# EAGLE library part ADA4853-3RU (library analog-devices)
Low Power, Rail-to-Rail Output, Video Op Amps with Ultralow Power Source: http://www.analog.com/static/imported-files/data_sheets/ADA4853-1_4853-2_4853-3.pdf
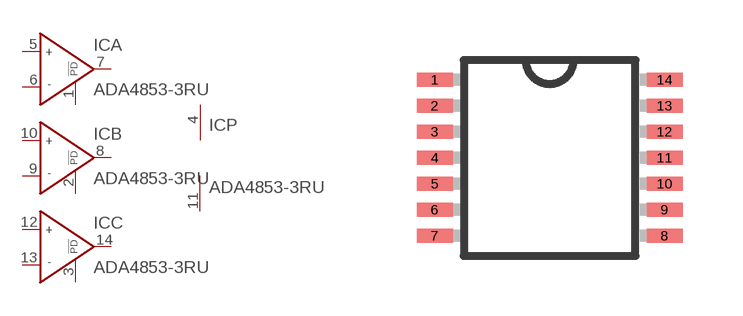
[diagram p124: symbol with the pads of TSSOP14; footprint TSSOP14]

Designator prefix IC; gates A=OP_PD B=OP_PD C=OP_PD P=PWR+-

## ADA4853-3RU (MPN: ADA4853-3YRUZ; OC_FARNELL: 1498692; OC_NEWARK: 15P0326)  [TSSOP14]
1  A:!POWERDOWN  pas
2  B:!POWERDOWN  pas
3  C:!POWERDOWN  pas
4  P:V+  pwr
5  A:IN+  in
6  A:IN-  in
7  A:OUT  out
8  B:OUT  out
9  B:IN-  in
10  B:IN+  in
11  P:V-  pwr
12  C:IN+  in
13  C:IN-  in
14  C:OUT  out

## Footprint TSSOP14 (pad centres in mm)
14-Lead Thin Shrink Small Outline Package [TSSOP] Source: Analog Devices .. 780914713ADD8704_0.pdf
smd 0.9 x 0.35: 1 -2.875,1.95; 2 -2.875,1.3; 3 -2.875,0.65; 4 -2.875,0; 5 -2.875,-0.65; 6 -2.875,-1.3; 7 -2.875,-1.95; 8 2.875,-1.95; 9 2.875,-1.3; 10 2.875,-0.65; 11 2.875,0; 12 2.875,0.65; 13 2.875,1.3; 14 2.875,1.95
